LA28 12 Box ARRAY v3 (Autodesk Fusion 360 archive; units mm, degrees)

design "LA28 12 Box ARRAY" references "LA28 TOUR BLOCK", "LA28 RF1 Sheet Metal Assembly"
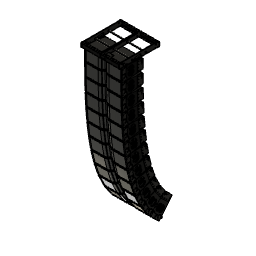
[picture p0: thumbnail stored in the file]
component_insert "Component Insert1"
as_built_joint "As-built1"
component_insert "Component Insert2"
joint "Assemble1" alignAngle 0 alignOffsetX 0 alignOffsetY 0 alignOffsetZ 5.08
component_insert "Component Insert3"
joint "Assemble2" alignAngle -0.5 alignOffsetX 0 alignOffsetY 0 alignOffsetZ 5.08
component_insert "Component Insert4"
component_insert "Component Insert5"
joint "Assemble3" alignAngle -1 alignOffsetX 0 alignOffsetY 0 alignOffsetZ 5.08
joint "Assemble4" alignAngle -1.5 alignOffsetX 0 alignOffsetY 0 alignOffsetZ 5.08
component_insert "Component Insert6"
component_insert "Component Insert7"
component_insert "Component Insert8"
joint "Assemble5" alignAngle -2 alignOffsetX 0 alignOffsetY 0 alignOffsetZ 5.08
joint "Assemble6" alignAngle -2 alignOffsetX 0 alignOffsetY 0 alignOffsetZ 5.08
joint "Assemble7" alignAngle -3 alignOffsetX 0 alignOffsetY 0 alignOffsetZ 5.08
component_insert "Component Insert9"
joint "Assemble8" alignAngle -4 alignOffsetX 0 alignOffsetY 0 alignOffsetZ 5.08
component_insert "Component Insert10"
joint "Assemble9" alignAngle -5 alignOffsetX 0 alignOffsetY 0 alignOffsetZ 5.08
component_insert "Component Insert11"
component_insert "Component Insert12"
joint "Assemble10" alignAngle -7 alignOffsetX 0 alignOffsetY 0 alignOffsetZ 5.08
joint "Assemble11" alignAngle -9 alignOffsetX 0 alignOffsetY 0 alignOffsetZ 5.08
component_insert "Component Insert13"
joint "Assemble12" alignAngle -11 alignOffsetX 0 alignOffsetY 0 alignOffsetZ 5.08

design "LA28 TOUR BLOCK" references "LA28 TOUR BLOCK.sldprt"
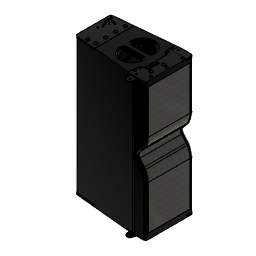
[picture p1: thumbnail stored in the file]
step "WorkingModel"
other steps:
derived_base_feature "Derived Base Feature" bodies "Fillet3"
named bodies: "Fillet3"

design "la28RF1 SHEET METAL ASSEMBLY.SLDASM"
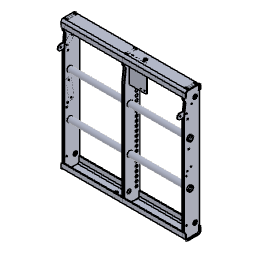
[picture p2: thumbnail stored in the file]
named bodies: "Cut-Extrude3", "Cut-Extrude2", "Mirror2", "Boss-Extrude1"

design "LA28 RF1 Sheet Metal Assembly" references "la28RF1 SHEET METAL ASSEMBLY.SLDASM"
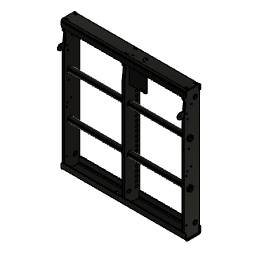
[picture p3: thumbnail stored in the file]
step "WorkingModel"
derived_instance "DerivedInstance1"
derived_instance "DerivedInstance2"
derived_instance "DerivedInstance3"
derived_instance "DerivedInstance4"
derived_instance "DerivedInstance5"
derived_instance "DerivedInstance6"
derived_instance "DerivedInstance7"
as_built_joint "As-built1"
offset_faces "OffsetFaces1" distance 0.7595 (= "0.1644 in - 0.1345 in")
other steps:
derived_base_feature "Derived Base Feature1"
derived_base_feature "Derived Base Feature1" bodies "Cut-Extrude3"
derived_base_feature "Derived Base Feature1" bodies "Cut-Extrude3"
derived_base_feature "Derived Base Feature1" bodies "Boss-Extrude1"
derived_base_feature "Derived Base Feature1" bodies "Cut-Extrude2"
derived_base_feature "Derived Base Feature1" bodies "Boss-Extrude1"
derived_base_feature "Derived Base Feature1" bodies "Cut-Extrude2"
derived_base_feature "Derived Base Feature1" bodies "Mirror2"
create_component "CreateComponent1"
create_component "CreateComponent2"
create_component "CreateComponent3"
create_component "CreateComponent4"
create_component "CreateComponent5"
create_component "CreateComponent6"
create_component "CreateComponent7"
named bodies: "Cut-Extrude3", "Cut-Extrude2", "Mirror2", "Boss-Extrude1"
